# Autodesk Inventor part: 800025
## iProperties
Created: 2007-11
Part Number: 800025
Document SubType Name: Modeling
Designer: TH
Density: 7.85 g/cm^3
Mass: 11.5096 g
Surface Area: 11.3549 cm^2
Volume: 1.46619 cm^3
Material: Steel
Description: NUT R3423 - M12
Component Category: Fasteners
Author: TH
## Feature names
1. Extrusion1
2. Extrusion2
3. Fillet1
